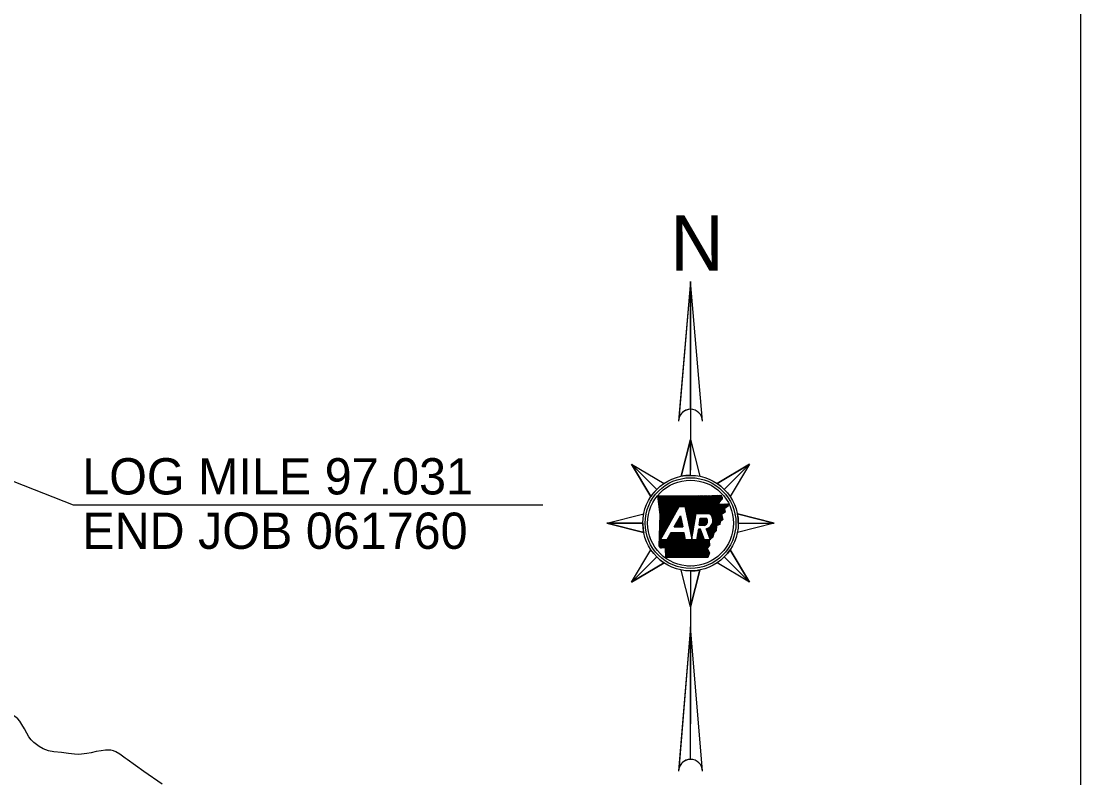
# Model space of a CAD drawing. Extents: x 22866 to 28196, y 1324810 to 1328105.
# Drawn here: x 26169 to 27046, y 1325963 to 1326588 of the extents above; entities that cross this region are included whole.
import ezdxf

# ---------------------------------------------------------------- set-up
doc = ezdxf.new("R2010")
doc.units = 0
for name, color, linetype in [('Level 31', 7, 'Continuous'), ('Page Text', 7, 'Continuous'), ('R_Border', 7, 'Continuous'), ('R_Draft', 7, 'Continuous')]:
    doc.layers.add(name, color=color, linetype=linetype)

msp = doc.modelspace()

# ---------------------------------------------------------------- linework, layer by layer
at = {"layer": 'Level 31'}
for points in [[(26173.49, 1325999.43), (26171.46, 1326003.22), (26169.39, 1326006.63), (26167.55, 1326009.39), (26165.98, 1326011.39), (26164.22, 1326012.88), (26162.12, 1326014.26), (26159.14, 1326015.8)], [(26256.38, 1325977.83), (26254.77, 1325978.87), (26250.29, 1325982.16), (26247.07, 1325984.16), (26245.08, 1325985), (26242.82, 1325985.5), (26240.22, 1325985.61), (26238.53, 1325985.5), (26234.86, 1325984.96), (26230.84, 1325984.31), (26226.53, 1325983.35), (26223.05, 1325982.7), (26218.76, 1325982.05), (26216.04, 1325981.93), (26212.9, 1325982.21), (26208.04, 1325982.66), (26202.04, 1325983.53), (26195.88, 1325984.22), (26191.32, 1325984.91), (26187.07, 1325986.64), (26183.74, 1325988.44), (26179.18, 1325991.69), (26176.93, 1325994.07), (26175.09, 1325996.6), (26173.49, 1325999.43)], [(26285.49, 1325957.26), (26270.28, 1325967.85), (26256.38, 1325977.83)]]:
    msp.add_lwpolyline(points, dxfattribs=at)
at = {"layer": 'Page Text'}
msp.add_line((26211.65, 1326188.26), (26600.38, 1326188.26), dxfattribs=at)
msp.add_lwpolyline([(25620.91, 1326420.53), (26211.65, 1326188.26)], dxfattribs=at)
at = {"layer": 'R_Border'}
msp.add_line((27045.59, 1325448.4), (27045.59, 1327502.95), dxfattribs=at)
at = {"layer": 'R_Draft'}
for p, q in [((26722.64, 1326373.08), (26712.91, 1326259.16)), ((26722.64, 1326373.08), (26722.64, 1326217.06)), ((26722.64, 1326267.36), (26722.64, 1326373.08)), ((26713.04, 1326260.75), (26713.49, 1326261.19)), ((26713.09, 1326261.36), (26714, 1326262.26)), ((26722.64, 1326242.39), (26714.95, 1326211.99)), ((26722.64, 1326212.75), (26722.64, 1326242.39)), ((26673.74, 1326222.13), (26694.7, 1326201.17)), ((26694.7, 1326201.17), (26673.74, 1326222.13)), ((26673.74, 1326222.13), (26689.79, 1326195.19)), ((26771.55, 1326222.13), (26744.61, 1326206.08)), ((26750.59, 1326201.17), (26771.55, 1326222.13)), ((26750.59, 1326201.17), (26771.55, 1326222.13)), ((26695.71, 1326195.5), (26696.05, 1326195.85)), ((26695.83, 1326194.51), (26697.17, 1326195.85)), ((26695.95, 1326193.51), (26698.29, 1326195.85)), ((26696.08, 1326192.52), (26699.41, 1326195.85)), ((26696.2, 1326191.52), (26700.52, 1326195.84)), ((26696.32, 1326190.53), (26701.64, 1326195.84)), ((26696.45, 1326189.54), (26702.76, 1326195.84)), ((26696.57, 1326188.54), (26703.87, 1326195.84)), ((26696.7, 1326187.55), (26704.99, 1326195.84)), ((26696.82, 1326186.55), (26706.11, 1326195.84)), ((26696.94, 1326185.56), (26707.22, 1326195.84)), ((26697.07, 1326184.56), (26708.34, 1326195.84)), ((26697.19, 1326183.57), (26709.46, 1326195.84)), ((26697.31, 1326182.58), (26710.58, 1326195.84)), ((26697.35, 1326171.44), (26721.78, 1326195.86)), ((26697.39, 1326172.59), (26720.66, 1326195.86)), ((26697.43, 1326173.75), (26719.54, 1326195.86)), ((26697.44, 1326181.58), (26711.7, 1326195.84)), ((26697.47, 1326174.9), (26718.42, 1326195.85)), ((26697.51, 1326176.06), (26717.3, 1326195.85)), ((26697.54, 1326177.22), (26716.18, 1326195.85)), ((26697.56, 1326180.59), (26712.82, 1326195.84)), ((26697.58, 1326178.37), (26715.06, 1326195.85)), ((26697.62, 1326179.53), (26713.94, 1326195.84)), ((26713.95, 1326186.92), (26722.9, 1326195.86)), ((26715.07, 1326186.92), (26724.02, 1326195.87)), ((26716.19, 1326186.92), (26725.14, 1326195.88)), ((26717.3, 1326186.92), (26726.28, 1326195.89)), ((26718, 1326186.5), (26727.42, 1326195.91)), ((26718.2, 1326185.58), (26728.55, 1326195.93)), ((26718.4, 1326184.65), (26729.69, 1326195.95)), ((26718.59, 1326183.73), (26730.82, 1326195.96)), ((26718.79, 1326182.81), (26731.96, 1326195.98)), ((26718.99, 1326181.89), (26733.09, 1326196)), ((26719.18, 1326180.97), (26734.23, 1326196.02)), ((26719.38, 1326180.05), (26735.36, 1326196.03)), ((26719.58, 1326179.13), (26736.5, 1326196.05)), ((26719.77, 1326178.21), (26737.63, 1326196.07)), ((26719.97, 1326177.29), (26738.77, 1326196.09)), ((26720.17, 1326176.37), (26739.91, 1326196.1)), ((26720.37, 1326175.45), (26741.04, 1326196.13)), ((26720.56, 1326174.53), (26742.19, 1326196.15)), ((26728.33, 1326181.17), (26743.33, 1326196.18)), ((26729.45, 1326181.17), (26744.48, 1326196.21)), ((26730.56, 1326181.17), (26745.62, 1326196.23)), ((26731.68, 1326181.17), (26746.77, 1326196.26)), ((26732.8, 1326181.17), (26747.91, 1326196.28)), ((26733.92, 1326181.17), (26748.16, 1326195.42)), ((26735.03, 1326181.17), (26748.7, 1326194.84)), ((26736.15, 1326181.17), (26748.84, 1326193.87)), ((26697.28, 1326169.12), (26710.94, 1326182.79)), ((26697.31, 1326170.28), (26712.4, 1326185.36)), ((26697.68, 1326159.38), (26713.28, 1326186.92)), ((26713.28, 1326186.92), (26717.91, 1326186.92)), ((26737.27, 1326181.17), (26746.29, 1326190.2)), ((26738.29, 1326181.07), (26746.07, 1326188.86)), ((26738.9, 1326180.56), (26747.25, 1326188.92)), ((26739.44, 1326179.99), (26748.43, 1326188.98)), ((26739.92, 1326179.36), (26749.61, 1326189.04)), ((26740.34, 1326178.65), (26750.79, 1326189.1)), ((26740.68, 1326177.88), (26751.96, 1326189.16)), ((26740.86, 1326173.59), (26751.01, 1326183.73)), ((26740.94, 1326177.02), (26753.03, 1326189.1)), ((26741.09, 1326176.05), (26753.55, 1326188.51)), ((26741.1, 1326174.94), (26750.88, 1326184.72)), ((26749.76, 1326181.36), (26751.14, 1326182.74)), ((26753.05, 1326186.89), (26754.07, 1326187.91)), ((26653.48, 1326173.22), (26683.12, 1326173.22)), ((26683.12, 1326173.22), (26653.48, 1326173.22)), ((26653.48, 1326173.22), (26683.88, 1326165.53)), ((26697.16, 1326165.66), (26706.56, 1326175.06)), ((26697.2, 1326166.81), (26708.02, 1326177.63)), ((26697.24, 1326167.97), (26709.48, 1326180.21)), ((26709.15, 1326170.19), (26714.25, 1326179.2)), ((26709.21, 1326170.19), (26714.95, 1326175.93)), ((26710.33, 1326170.19), (26715.15, 1326175.01)), ((26710.54, 1326172.64), (26714.76, 1326176.85)), ((26711.44, 1326170.19), (26715.35, 1326174.09)), ((26712, 1326175.22), (26714.56, 1326177.77)), ((26712.56, 1326170.19), (26715.54, 1326173.17)), ((26713.46, 1326177.8), (26714.36, 1326178.7)), ((26720.76, 1326173.61), (26727.1, 1326179.95)), ((26720.96, 1326172.68), (26726.87, 1326178.59)), ((26721.15, 1326171.76), (26726.63, 1326177.24)), ((26721.35, 1326170.84), (26726.39, 1326175.89)), ((26721.55, 1326169.92), (26726.16, 1326174.53)), ((26721.74, 1326169), (26725.92, 1326173.18)), ((26727.32, 1326181.17), (26738.14, 1326181.17)), ((26729.67, 1326171.41), (26735.55, 1326177.29)), ((26729.9, 1326172.75), (26734.44, 1326177.29)), ((26730.14, 1326174.11), (26733.32, 1326177.29)), ((26730.37, 1326175.46), (26732.2, 1326177.29)), ((26730.61, 1326176.81), (26731.08, 1326177.29)), ((26730.69, 1326177.29), (26735.78, 1326177.29)), ((26730.79, 1326171.41), (26736.18, 1326176.79)), ((26731.91, 1326171.41), (26736.55, 1326176.05)), ((26733.03, 1326171.41), (26736.76, 1326175.14)), ((26734.14, 1326171.41), (26736.67, 1326173.93)), ((26736.25, 1326166.74), (26748.64, 1326179.13)), ((26736.55, 1326165.92), (26748.85, 1326178.22)), ((26736.85, 1326165.1), (26749.06, 1326177.31)), ((26737.15, 1326164.29), (26749.27, 1326176.4)), ((26739.89, 1326171.5), (26748.43, 1326180.04)), ((26791.8, 1326173.22), (26761.41, 1326180.92)), ((26762.16, 1326173.22), (26791.8, 1326173.22)), ((26762.16, 1326173.22), (26791.8, 1326173.22)), ((26697.01, 1326161.03), (26700.72, 1326164.75)), ((26697.05, 1326162.19), (26702.18, 1326167.32)), ((26697.08, 1326163.34), (26703.64, 1326169.9)), ((26697.12, 1326164.5), (26705.1, 1326172.48)), ((26697.21, 1326153.41), (26708.96, 1326165.16)), ((26697.88, 1326152.96), (26710.08, 1326165.16)), ((26698.68, 1326152.64), (26711.19, 1326165.16)), ((26700.01, 1326152.85), (26712.31, 1326165.16)), ((26701.14, 1326152.87), (26713.43, 1326165.16)), ((26702.02, 1326152.63), (26714.55, 1326165.16)), ((26702.05, 1326151.55), (26715.67, 1326165.16)), ((26702.06, 1326150.43), (26716.78, 1326165.16)), ((26702.06, 1326149.32), (26717.37, 1326164.63)), ((26706.31, 1326165.16), (26703.03, 1326159.38)), ((26704.3, 1326161.62), (26707.84, 1326165.16)), ((26705.76, 1326164.2), (26706.72, 1326165.16)), ((26717.26, 1326165.16), (26706.31, 1326165.16)), ((26709.15, 1326170.19), (26716.18, 1326170.19)), ((26713.68, 1326170.19), (26715.74, 1326172.25)), ((26714.8, 1326170.19), (26715.94, 1326171.33)), ((26715.92, 1326170.19), (26716.14, 1326170.41)), ((26721.94, 1326168.08), (26725.69, 1326171.83)), ((26722.14, 1326167.16), (26725.45, 1326170.47)), ((26722.34, 1326166.24), (26725.22, 1326169.12)), ((26722.53, 1326165.32), (26724.98, 1326167.76)), ((26722.73, 1326164.4), (26724.74, 1326166.41)), ((26722.93, 1326163.48), (26724.51, 1326165.06)), ((26727.76, 1326160.49), (26732.17, 1326164.9)), ((26728, 1326161.84), (26731.87, 1326165.71)), ((26728.24, 1326163.2), (26731.57, 1326166.53)), ((26728.47, 1326164.55), (26731.27, 1326167.34)), ((26728.71, 1326165.9), (26730.94, 1326168.14)), ((26728.94, 1326167.26), (26729.82, 1326168.14)), ((26730.97, 1326168.14), (26729.1, 1326168.14)), ((26729.67, 1326171.41), (26734.31, 1326171.41)), ((26734.21, 1326159.38), (26730.97, 1326168.14)), ((26735.56, 1326168.61), (26738.97, 1326159.38)), ((26735.64, 1326168.37), (26735.98, 1326168.71)), ((26735.95, 1326167.55), (26738.07, 1326169.68)), ((26737.45, 1326163.47), (26744.16, 1326170.18)), ((26737.76, 1326162.66), (26744.03, 1326168.93)), ((26738.06, 1326161.84), (26743.91, 1326167.69)), ((26738.36, 1326161.02), (26741.79, 1326164.45)), ((26745.45, 1326171.46), (26747.01, 1326173.03)), ((26696.79, 1326154.11), (26702.06, 1326159.38)), ((26696.81, 1326155.25), (26700.95, 1326159.38)), ((26696.85, 1326156.41), (26699.83, 1326159.38)), ((26696.89, 1326157.56), (26698.71, 1326159.38)), ((26696.93, 1326158.72), (26697.8, 1326159.59)), ((26696.97, 1326159.87), (26699.26, 1326162.17)), ((26703.03, 1326159.38), (26697.68, 1326159.38)), ((26702.06, 1326148.2), (26717.57, 1326163.71)), ((26702.07, 1326147.09), (26717.77, 1326162.79)), ((26702.07, 1326145.97), (26717.96, 1326161.87)), ((26702.09, 1326144.87), (26718.16, 1326160.95)), ((26703.2, 1326144.87), (26718.36, 1326160.03)), ((26704.32, 1326144.87), (26718.83, 1326159.38)), ((26705.43, 1326144.87), (26719.95, 1326159.38)), ((26706.55, 1326144.86), (26721.07, 1326159.38)), ((26707.67, 1326144.86), (26722.18, 1326159.38)), ((26708.78, 1326144.86), (26723.3, 1326159.38)), ((26709.9, 1326144.86), (26724.42, 1326159.38)), ((26711.01, 1326144.86), (26725.54, 1326159.38)), ((26712.13, 1326144.86), (26726.65, 1326159.38)), ((26713.25, 1326144.85), (26732.47, 1326164.08)), ((26714.36, 1326144.85), (26732.77, 1326163.26)), ((26715.48, 1326144.85), (26733.08, 1326162.45)), ((26716.59, 1326144.85), (26733.38, 1326161.63)), ((26717.71, 1326144.85), (26733.68, 1326160.82)), ((26727.57, 1326159.38), (26718.5, 1326159.38)), ((26718.83, 1326144.84), (26733.98, 1326160)), ((26719.94, 1326144.84), (26734.48, 1326159.38)), ((26721.06, 1326144.84), (26735.6, 1326159.38)), ((26722.17, 1326144.84), (26736.72, 1326159.38)), ((26723.12, 1326162.56), (26724.27, 1326163.7)), ((26723.29, 1326144.84), (26737.83, 1326159.38)), ((26723.32, 1326161.64), (26724.04, 1326162.35)), ((26723.52, 1326160.71), (26723.8, 1326161)), ((26724.41, 1326144.84), (26738.21, 1326158.64)), ((26725.52, 1326144.83), (26738.26, 1326157.57)), ((26726.64, 1326144.83), (26738.31, 1326156.5)), ((26738.97, 1326159.38), (26734.21, 1326159.38)), ((26738.66, 1326160.21), (26741.31, 1326162.85)), ((26727.75, 1326144.83), (26738.36, 1326155.43)), ((26728.87, 1326144.83), (26736.52, 1326152.48)), ((26729.99, 1326144.83), (26736.87, 1326151.71)), ((26731.1, 1326144.82), (26737.21, 1326150.93)), ((26732.22, 1326144.82), (26737.56, 1326150.16)), ((26733.33, 1326144.82), (26737.9, 1326149.39)), ((26734.45, 1326144.82), (26738.19, 1326148.56)), ((26735.57, 1326144.82), (26737.68, 1326146.94)), ((26771.55, 1326124.32), (26755.5, 1326151.26)), ((26673.74, 1326124.32), (26694.7, 1326145.28)), ((26694.7, 1326145.28), (26673.74, 1326124.32)), ((26673.74, 1326124.32), (26700.68, 1326140.37)), ((26736.68, 1326144.82), (26737.18, 1326145.31)), ((26750.59, 1326145.28), (26771.55, 1326124.32)), ((26750.59, 1326145.28), (26771.55, 1326124.32)), ((26722.64, 1326104.06), (26730.34, 1326134.46)), ((26722.64, 1326133.7), (26722.64, 1326133.71)), ((26722.64, 1326133.7), (26722.64, 1326007.19)), ((26722.64, 1326133.7), (26722.64, 1326104.06)), ((26722.64, 1326087.54), (26712.9, 1325969.62)), ((26722.64, 1325977.87), (26722.64, 1326087.54))]:
    msp.add_line(p, q, dxfattribs=at)
for points in [[(26732.52, 1326257.48), (26722.64, 1326373.08), (26712.76, 1326257.48)], [(26714.95, 1326211.99), (26722.64, 1326242.39), (26730.34, 1326211.99)], [(26689.79, 1326195.19), (26673.74, 1326222.13), (26700.68, 1326206.08)], [(26744.61, 1326206.08), (26771.55, 1326222.13), (26755.5, 1326195.19)], [(26695.66, 1326195.85), (26711.08, 1326195.84), (26724.62, 1326195.87), (26740.58, 1326196.11), (26747.98, 1326196.29)], [(26696.78, 1326154.12), (26697.64, 1326180), (26695.66, 1326195.85)], [(26717.91, 1326186.92), (26723.65, 1326160.12), (26727.32, 1326181.17)], [(26752.83, 1326189.2), (26754.16, 1326187.81), (26750.83, 1326185.07), (26751.19, 1326182.31), (26748.34, 1326180.43), (26749.32, 1326176.18), (26747.12, 1326174.18), (26746.92, 1326172), (26744.25, 1326171.03), (26743.83, 1326166.92), (26741.91, 1326164.86), (26740.98, 1326161.76), (26738.18, 1326159.2), (26738.39, 1326154.68), (26736.49, 1326152.55), (26738.22, 1326148.67), (26737.02, 1326144.82)], [(26745.69, 1326188.84), (26752.93, 1326189.21)], [(26683.88, 1326165.53), (26653.48, 1326173.22), (26683.88, 1326180.92)], [(26714.25, 1326179.2), (26716.18, 1326170.19)], [(26729.67, 1326171.41), (26730.69, 1326177.29)], [(26761.41, 1326180.92), (26791.8, 1326173.22), (26761.41, 1326165.53)], [(26718.5, 1326159.38), (26717.26, 1326165.16)], [(26729.1, 1326168.14), (26727.57, 1326159.38)], [(26700.68, 1326140.37), (26673.74, 1326124.32), (26689.79, 1326151.26)], [(26737.02, 1326144.82), (26702.07, 1326144.87), (26702.05, 1326152.59)], [(26755.5, 1326151.26), (26771.55, 1326124.32), (26744.61, 1326140.37)], [(26730.34, 1326134.46), (26722.64, 1326104.06), (26714.95, 1326134.46)], [(26732.52, 1325967.99), (26722.64, 1326087.54), (26712.76, 1325967.99)]]:
    msp.add_lwpolyline(points, dxfattribs=at)
for radius in [39.52, 37.54, 35.57]:
    msp.add_circle((26722.64, 1326173.22), radius, dxfattribs=at)
for centre, radius, start, end in [((26722.64, 1326257.48), 9.88, 0, 180), ((26722.64, 1326257.48), 9.88, 90, 170.22959), ((26722.64, 1326173.22), 39.52, 90, 101.22909), ((26722.64, 1326173.22), 39.52, 135, 146.22909), ((26722.64, 1326173.22), 39.52, 45, 56.22909), ((26722.64, 1326173.22), 39.52, 180, 191.22909), ((26733.2, 1326174.81), 3.58, 288.12683, 43.89016), ((26734.12, 1326175.45), 7, 281.86262, 54.87052), ((26722.64, 1326173.22), 39.52, 0, 11.22909), ((26722.64, 1326173.22), 39.52, 315, 326.22909), ((26722.64, 1326173.22), 39.52, 225, 236.22909), ((26722.64, 1326173.22), 39.52, 270, 281.22909), ((26722.64, 1325967.99), 9.88, 0, 180), ((26722.64, 1325967.99), 9.88, 90, 170.5511)]:
    msp.add_arc(centre, radius, start, end, dxfattribs=at)
for points in [[(26747.98, 1326196.29), (26748.03, 1326195.87), (26748.16, 1326195.65), (26748.18, 1326195.25), (26748.34, 1326195.08), (26748.62, 1326194.9), (26748.87, 1326194.63), (26748.93, 1326194.3), (26748.85, 1326193.97), (26748.83, 1326193.6), (26748.79, 1326193.27), (26748.74, 1326192.98), (26748.51, 1326192.74), (26748.29, 1326192.57), (26748.09, 1326192.37), (26747.94, 1326192.16), (26747.7, 1326191.93), (26747.45, 1326191.69), (26747.25, 1326191.48), (26747.05, 1326191.21), (26746.95, 1326190.92), (26746.73, 1326190.71), (26746.56, 1326190.52), (26746.33, 1326190.26), (26746.22, 1326190), (26746, 1326189.71), (26745.95, 1326189.42), (26745.81, 1326189.19), (26745.8, 1326189.15)], [(26702.05, 1326152.59), (26702.09, 1326152.57), (26701.91, 1326152.69), (26701.66, 1326152.82), (26701.38, 1326152.84), (26701.03, 1326152.88), (26700.74, 1326152.91), (26700.43, 1326153.11), (26700.11, 1326152.9), (26699.74, 1326152.75), (26699.53, 1326152.92), (26699.26, 1326152.81), (26699.07, 1326152.86), (26698.73, 1326152.64), (26698.42, 1326152.72), (26698.19, 1326152.65), (26697.9, 1326152.66), (26697.85, 1326152.99), (26697.57, 1326153.04), (26697.33, 1326153.17), (26697.17, 1326153.5), (26697.05, 1326153.76), (26696.78, 1326154.12)]]:
    msp.add_spline(points, degree=3, dxfattribs=at)

# ---------------------------------------------------------------- texts
at = {"layer": 'Page Text'}
for s, p in [('LOG MILE 97.031', (26219.27, 1326196.95)), ('END JOB 061760', (26219.27, 1326151.95))]:
    msp.add_text(s, height=30, dxfattribs=at).set_placement(p)
at = {"layer": 'R_Draft'}
for s, height, p in [('N', 45.6, (26705.98, 1326382.05)), ('DWB 7-27-17', 0.7685, (26720.22, 1326137))]:
    msp.add_text(s, height=height, dxfattribs=at).set_placement(p)

doc.saveas('drawing.dxf')
